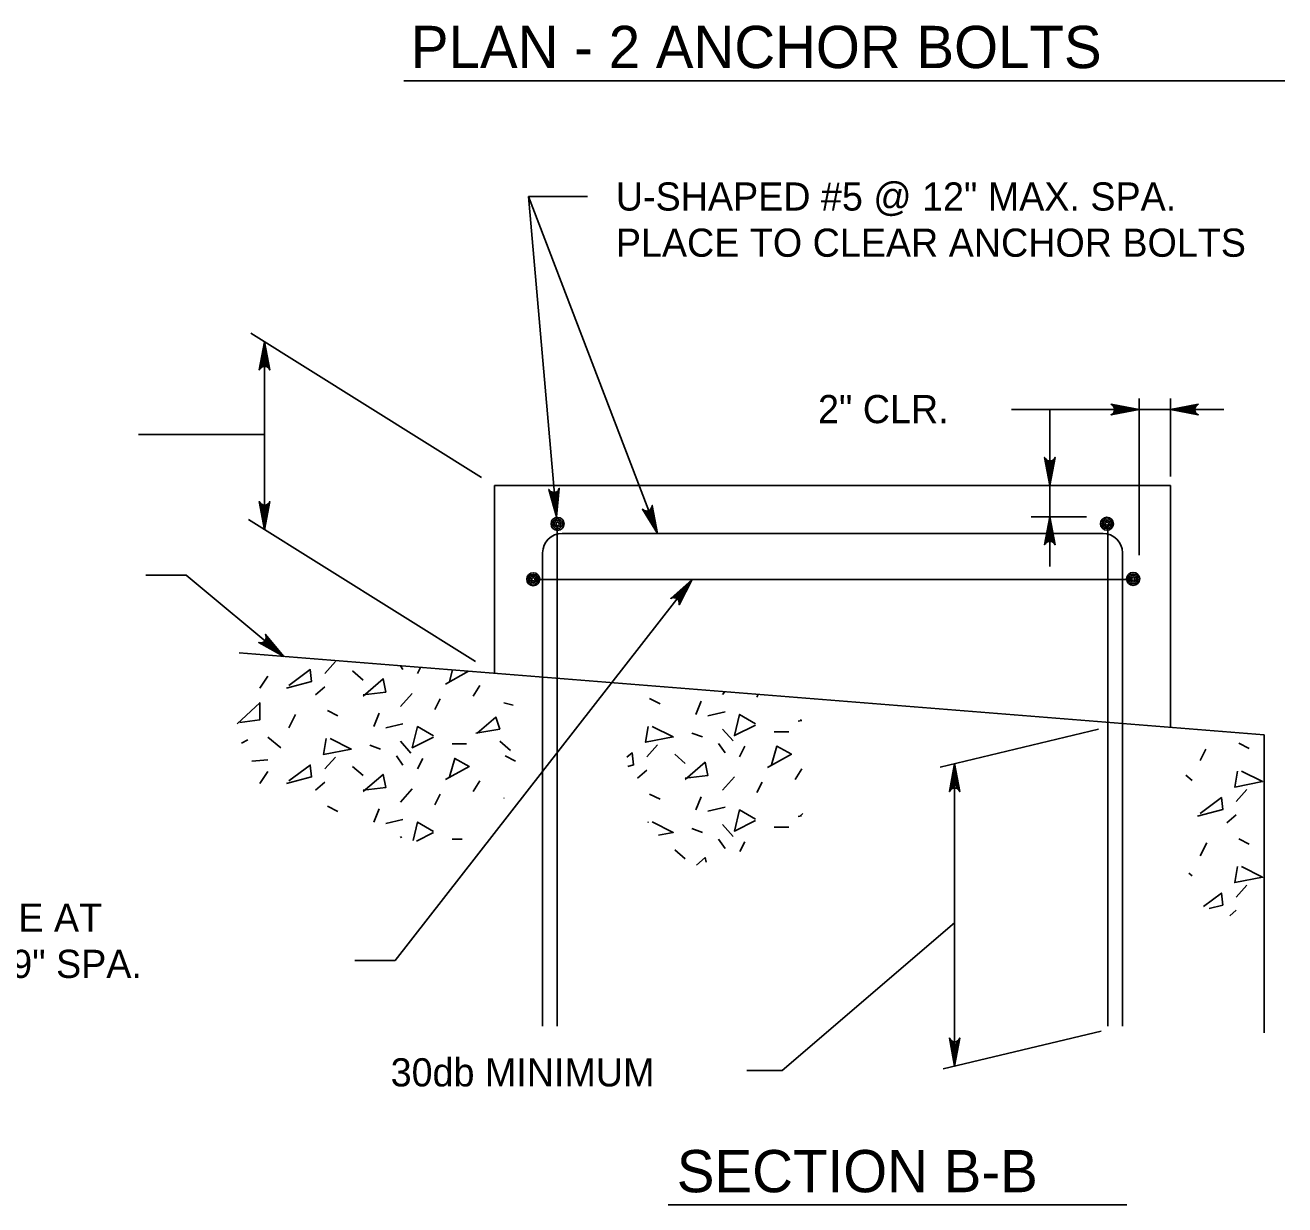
# Model space of a CAD drawing. Extents: x 646165 to 651486, y 296916 to 299292.
# Drawn here: x 651041.6 to 651175.7, y 298407.2 to 298532.8 of the extents above; entities that cross this region are included whole.
import ezdxf

# ---------------------------------------------------------------- set-up
doc = ezdxf.new("R2010")
doc.units = 0
for name, color, linetype in [('51', 7, 'Continuous'), ('52', 7, 'Continuous'), ('53', 7, 'Continuous'), ('54', 7, 'Continuous'), ('56', 7, 'Continuous')]:
    doc.layers.add(name, color=color, linetype=linetype)

msp = doc.modelspace()

# ---------------------------------------------------------------- linework, layer by layer
at = {"layer": '51'}
for p, q in [((651091.55, 298483.8), (651091.55, 298463.8)), ((651091.55, 298483.8), (651163.51, 298483.8)), ((651163.51, 298483.8), (651163.51, 298458.05)), ((651064.36, 298465.98), (651173.51, 298457.25)), ((651173.51, 298457.25), (651173.51, 298425.51))]:
    msp.add_line(p, q, dxfattribs=at)
at = {"layer": '52'}
for p, q in [((651095.17, 298514.57), (651101.44, 298514.57)), ((651095.17, 298514.57), (651098.14, 298480.47)), ((651095.17, 298514.57), (651108.88, 298478.69)), ((651065.6, 298500.01), (651090.17, 298484.66)), ((651067.05, 298499.1), (651067.05, 298479.1)), ((651160.18, 298493.07), (651160.18, 298476.38)), ((651163.51, 298493.07), (651163.51, 298484.77)), ((651146.58, 298491.89), (651169.19, 298491.89)), ((651150.68, 298491.89), (651150.68, 298475.18)), ((651053.63, 298489.22), (651067.05, 298489.22)), ((651148.69, 298480.47), (651154.57, 298480.47)), ((651065.35, 298480.17), (651089.52, 298465.07)), ((651054.42, 298474.26), (651058.71, 298474.26)), ((651069.09, 298465.6), (651058.71, 298474.26)), ((651080.96, 298433.22), (651112.58, 298473.8)), ((651138.98, 298453.82), (651155.85, 298457.85)), ((651140.54, 298454.19), (651140.54, 298421.98)), ((651122.17, 298421.51), (651140.54, 298437.23)), ((651076.67, 298433.22), (651080.96, 298433.22)), ((651139.33, 298421.69), (651156.13, 298425.7)), ((651118.41, 298421.51), (651122.17, 298421.51))]:
    msp.add_line(p, q, dxfattribs=at)
for points in [[(651067.05, 298499.1), (651067.61, 298496.12), (651067.53, 298496.24), (651067.45, 298496.35), (651067.35, 298496.41), (651067.25, 298496.47), (651067.15, 298496.49), (651067.05, 298496.5), (651066.95, 298496.49), (651066.85, 298496.47), (651066.75, 298496.41), (651066.65, 298496.35), (651066.57, 298496.24), (651066.49, 298496.12), (651067.05, 298499.1), (651066.57, 298496.24), (651066.65, 298496.35), (651067.05, 298499.1), (651066.75, 298496.41), (651066.85, 298496.47), (651067.05, 298499.1), (651066.95, 298496.49), (651067.05, 298496.5), (651067.05, 298499.1), (651067.15, 298496.49), (651067.25, 298496.47), (651067.05, 298499.1), (651067.35, 298496.41), (651067.45, 298496.35), (651067.05, 298499.1), (651067.53, 298496.24)], [(651160.18, 298491.89), (651157.2, 298491.33), (651157.31, 298491.41), (651157.43, 298491.49), (651157.48, 298491.59), (651157.54, 298491.69), (651157.56, 298491.79), (651157.58, 298491.89), (651157.56, 298491.99), (651157.54, 298492.09), (651157.48, 298492.19), (651157.43, 298492.29), (651157.31, 298492.37), (651157.2, 298492.45), (651160.18, 298491.89), (651157.31, 298492.37), (651157.43, 298492.29), (651160.18, 298491.89), (651157.48, 298492.19), (651157.54, 298492.09), (651160.18, 298491.89), (651157.56, 298491.99), (651157.58, 298491.89), (651160.18, 298491.89), (651157.56, 298491.79), (651157.54, 298491.69), (651160.18, 298491.89), (651157.48, 298491.59), (651157.43, 298491.49), (651160.18, 298491.89), (651157.31, 298491.41)], [(651163.51, 298491.89), (651166.49, 298492.45), (651166.38, 298492.37), (651166.26, 298492.29), (651166.2, 298492.19), (651166.15, 298492.09), (651166.13, 298491.99), (651166.11, 298491.89), (651166.13, 298491.79), (651166.15, 298491.69), (651166.2, 298491.59), (651166.26, 298491.49), (651166.38, 298491.41), (651166.49, 298491.33), (651163.51, 298491.89), (651166.38, 298491.41), (651166.26, 298491.49), (651163.51, 298491.89), (651166.2, 298491.59), (651166.15, 298491.69), (651163.51, 298491.89), (651166.13, 298491.79), (651166.11, 298491.89), (651163.51, 298491.89), (651166.13, 298491.99), (651166.15, 298492.09), (651163.51, 298491.89), (651166.2, 298492.19), (651166.26, 298492.29), (651163.51, 298491.89), (651166.38, 298492.37)], [(651150.68, 298483.8), (651150.12, 298486.79), (651150.2, 298486.67), (651150.28, 298486.56), (651150.38, 298486.5), (651150.48, 298486.44), (651150.58, 298486.42), (651150.68, 298486.4), (651150.78, 298486.42), (651150.88, 298486.44), (651150.98, 298486.5), (651151.08, 298486.56), (651151.16, 298486.67), (651151.24, 298486.79), (651150.68, 298483.8), (651151.16, 298486.67), (651151.08, 298486.56), (651150.68, 298483.8), (651150.98, 298486.5), (651150.88, 298486.44), (651150.68, 298483.8), (651150.78, 298486.42), (651150.68, 298486.4), (651150.68, 298483.8), (651150.58, 298486.42), (651150.48, 298486.44), (651150.68, 298483.8), (651150.38, 298486.5), (651150.28, 298486.56), (651150.68, 298483.8), (651150.2, 298486.67)], [(651098.14, 298480.47), (651097.32, 298483.39), (651097.41, 298483.28), (651097.5, 298483.18), (651097.61, 298483.13), (651097.71, 298483.08), (651097.81, 298483.07), (651097.91, 298483.06), (651098.01, 298483.08), (651098.11, 298483.11), (651098.2, 298483.18), (651098.3, 298483.25), (651098.37, 298483.37), (651098.44, 298483.49), (651098.14, 298480.47), (651098.37, 298483.37), (651098.3, 298483.25), (651098.14, 298480.47), (651098.2, 298483.18), (651098.11, 298483.11), (651098.14, 298480.47), (651098.01, 298483.08), (651097.91, 298483.06), (651098.14, 298480.47), (651097.81, 298483.07), (651097.71, 298483.08), (651098.14, 298480.47), (651097.61, 298483.13), (651097.5, 298483.18), (651098.14, 298480.47), (651097.41, 298483.28)], [(651067.05, 298479.1), (651066.49, 298482.09), (651066.57, 298481.97), (651066.65, 298481.86), (651066.75, 298481.8), (651066.85, 298481.74), (651066.95, 298481.72), (651067.05, 298481.7), (651067.15, 298481.72), (651067.25, 298481.74), (651067.35, 298481.8), (651067.45, 298481.86), (651067.53, 298481.97), (651067.61, 298482.09), (651067.05, 298479.1), (651067.53, 298481.97), (651067.45, 298481.86), (651067.05, 298479.1), (651067.35, 298481.8), (651067.25, 298481.74), (651067.05, 298479.1), (651067.15, 298481.72), (651067.05, 298481.7), (651067.05, 298479.1), (651066.95, 298481.72), (651066.85, 298481.74), (651067.05, 298479.1), (651066.75, 298481.8), (651066.65, 298481.86), (651067.05, 298479.1), (651066.57, 298481.97)], [(651108.88, 298478.69), (651107.29, 298481.28), (651107.41, 298481.2), (651107.52, 298481.12), (651107.64, 298481.1), (651107.75, 298481.08), (651107.85, 298481.1), (651107.95, 298481.12), (651108.04, 298481.17), (651108.13, 298481.23), (651108.2, 298481.32), (651108.27, 298481.41), (651108.3, 298481.54), (651108.34, 298481.68), (651108.88, 298478.69), (651108.3, 298481.54), (651108.27, 298481.41), (651108.88, 298478.69), (651108.2, 298481.32), (651108.13, 298481.23), (651108.88, 298478.69), (651108.04, 298481.17), (651107.95, 298481.12), (651108.88, 298478.69), (651107.85, 298481.1), (651107.75, 298481.08), (651108.88, 298478.69), (651107.64, 298481.1), (651107.52, 298481.12), (651108.88, 298478.69), (651107.41, 298481.2)], [(651150.68, 298480.47), (651151.24, 298477.49), (651151.16, 298477.6), (651151.08, 298477.72), (651150.98, 298477.78), (651150.88, 298477.84), (651150.78, 298477.85), (651150.68, 298477.87), (651150.58, 298477.85), (651150.48, 298477.84), (651150.38, 298477.78), (651150.28, 298477.72), (651150.2, 298477.6), (651150.12, 298477.49), (651150.68, 298480.47), (651150.2, 298477.6), (651150.28, 298477.72), (651150.68, 298480.47), (651150.38, 298477.78), (651150.48, 298477.84), (651150.68, 298480.47), (651150.58, 298477.85), (651150.68, 298477.87), (651150.68, 298480.47), (651150.78, 298477.85), (651150.88, 298477.84), (651150.68, 298480.47), (651150.98, 298477.78), (651151.08, 298477.72), (651150.68, 298480.47), (651151.16, 298477.6)], [(651112.58, 298473.8), (651111.19, 298471.11), (651111.19, 298471.25), (651111.2, 298471.39), (651111.16, 298471.49), (651111.12, 298471.6), (651111.05, 298471.68), (651110.98, 298471.75), (651110.89, 298471.8), (651110.8, 298471.85), (651110.68, 298471.86), (651110.57, 298471.88), (651110.44, 298471.84), (651110.3, 298471.79), (651112.58, 298473.8), (651110.44, 298471.84), (651110.57, 298471.88), (651112.58, 298473.8), (651110.68, 298471.86), (651110.8, 298471.85), (651112.58, 298473.8), (651110.89, 298471.8), (651110.98, 298471.75), (651112.58, 298473.8), (651111.05, 298471.68), (651111.12, 298471.6), (651112.58, 298473.8), (651111.16, 298471.49), (651111.2, 298471.39), (651112.58, 298473.8), (651111.19, 298471.25)], [(651069.09, 298465.6), (651066.44, 298467.08), (651066.58, 298467.07), (651066.72, 298467.06), (651066.83, 298467.09), (651066.94, 298467.13), (651067.02, 298467.2), (651067.1, 298467.26), (651067.15, 298467.35), (651067.2, 298467.44), (651067.22, 298467.55), (651067.23, 298467.67), (651067.2, 298467.8), (651067.16, 298467.94), (651069.09, 298465.6), (651067.2, 298467.8), (651067.23, 298467.67), (651069.09, 298465.6), (651067.22, 298467.55), (651067.2, 298467.44), (651069.09, 298465.6), (651067.15, 298467.35), (651067.1, 298467.26), (651069.09, 298465.6), (651067.02, 298467.2), (651066.94, 298467.13), (651069.09, 298465.6), (651066.83, 298467.09), (651066.72, 298467.06), (651069.09, 298465.6), (651066.58, 298467.07)], [(651140.54, 298454.19), (651141.09, 298451.21), (651140.94, 298451.44), (651140.74, 298451.56), (651140.54, 298451.59), (651140.34, 298451.56), (651140.14, 298451.44), (651139.98, 298451.21), (651140.54, 298454.19), (651140.14, 298451.44), (651140.34, 298451.56), (651140.54, 298454.19), (651140.54, 298451.59), (651140.74, 298451.56), (651140.54, 298454.19), (651140.94, 298451.44)], [(651140.54, 298421.98), (651139.98, 298424.97), (651140.14, 298424.74), (651140.34, 298424.62), (651140.54, 298424.58), (651140.74, 298424.62), (651140.94, 298424.74), (651141.09, 298424.97), (651140.54, 298421.98), (651140.94, 298424.74), (651140.74, 298424.62), (651140.54, 298421.98), (651140.54, 298424.58), (651140.34, 298424.62), (651140.54, 298421.98), (651140.14, 298424.74)]]:
    msp.add_lwpolyline(points, dxfattribs=at)
at = {"layer": '53'}
for p, q in [((651081.87, 298526.91), (651175.7, 298526.91)), ((651110.03, 298407.21), (651158.87, 298407.21))]:
    msp.add_line(p, q, dxfattribs=at)
at = {"layer": '54'}
for p, q in [((651098.22, 298479.58), (651098.22, 298426.25)), ((651156.84, 298479.58), (651156.84, 298426.25)), ((651098.73, 298478.69), (651156.34, 298478.69)), ((651096.66, 298476.63), (651096.66, 298426.25)), ((651158.4, 298476.63), (651158.4, 298426.25)), ((651095.77, 298473.8), (651159.29, 298473.8))]:
    msp.add_line(p, q, dxfattribs=at)
for centre, radius in [((651098.25, 298479.72), 0.693), ((651156.76, 298479.74), 0.693), ((651098.25, 298479.72), 0.52), ((651098.25, 298479.72), 0.347), ((651098.25, 298479.72), 0.173), ((651156.76, 298479.74), 0.52), ((651156.76, 298479.74), 0.347), ((651156.76, 298479.74), 0.173), ((651095.66, 298473.82), 0.693), ((651095.66, 298473.82), 0.52), ((651095.66, 298473.82), 0.347), ((651095.66, 298473.82), 0.173), ((651159.55, 298473.85), 0.693), ((651159.55, 298473.85), 0.52), ((651159.55, 298473.85), 0.347), ((651159.55, 298473.85), 0.173)]:
    msp.add_circle(centre, radius, dxfattribs=at)
for centre, start, end in [((651098.73, 298476.63), 90, 180), ((651156.34, 298476.63), 0, 90)]:
    msp.add_arc(centre, 2.07, start, end, dxfattribs=at)
at = {"layer": '56'}
for p, q in [((651073.46, 298463.79), (651074.59, 298465.06)), ((651081.51, 298464.61), (651081.79, 298464.21)), ((651083.67, 298464.43), (651083.35, 298463.79)), ((651066.54, 298462.23), (651067.39, 298463.5)), ((651076.43, 298464.07), (651077.56, 298463.08)), ((651072.47, 298461.53), (651073.46, 298462.37)), ((651082.78, 298461.67), (651081.51, 298460.26)), ((651089.28, 298461.39), (651089.98, 298462.52)), ((651116.08, 298461.84), (651115.81, 298461.54)), ((651119.63, 298461.56), (651119.48, 298461.26)), ((651085.75, 298461.1), (651085.18, 298459.97)), ((651092.52, 298460.68), (651093.51, 298460.4)), ((651108.04, 298461.12), (651109.17, 298460.56)), ((651113.55, 298460.84), (651112.98, 298459.43)), ((651069.65, 298458), (651070.35, 298459.41)), ((651073.74, 298459.83), (651074.87, 298459.27)), ((651079.25, 298459.55), (651078.69, 298458.14)), ((651116.09, 298459.71), (651114.26, 298459.29)), ((651081.79, 298458.42), (651079.96, 298458)), ((651115.81, 298457.87), (651116.94, 298456.6)), ((651121.32, 298457.59), (651122.87, 298457.59)), ((651065.27, 298456.73), (651064.58, 298456.38)), ((651067.39, 298457.01), (651068.8, 298455.88)), ((651081.51, 298456.58), (651082.64, 298455.31)), ((651087.02, 298456.3), (651088.57, 298456.3)), ((651092.1, 298456.58), (651093.23, 298455.6)), ((651107.76, 298454.91), (651108.89, 298456.18)), ((651112.56, 298457.45), (651113.69, 298457.03)), ((651115.39, 298456.32), (651116.09, 298455.33)), ((651170.79, 298456.36), (651171.92, 298455.8)), ((651073.46, 298453.62), (651074.59, 298454.89)), ((651078.26, 298456.16), (651079.39, 298455.74)), ((651081.09, 298455.03), (651081.79, 298454.04)), ((651092.67, 298455.03), (651093.79, 298454.47)), ((651110.73, 298455.19), (651111.85, 298454.2)), ((651118.21, 298456.04), (651117.64, 298454.91)), ((651166.69, 298454.53), (651167.3, 298455.74)), ((651065.7, 298454.47), (651067.39, 298454.61)), ((651076.43, 298453.9), (651077.56, 298452.91)), ((651083.91, 298454.75), (651083.35, 298453.62)), ((651106.77, 298452.65), (651107.76, 298453.5)), ((651123.57, 298452.51), (651124.28, 298453.64)), ((651066.54, 298452.07), (651067.39, 298453.34)), ((651072.47, 298451.36), (651073.46, 298452.21)), ((651089.28, 298451.22), (651089.98, 298452.35)), ((651117.08, 298452.79), (651115.81, 298451.38)), ((651120.04, 298452.23), (651119.48, 298451.1)), ((651165.17, 298452.95), (651165.85, 298452.41)), ((651082.78, 298451.5), (651081.51, 298450.09)), ((651085.75, 298450.94), (651085.18, 298449.81)), ((651108.04, 298450.95), (651109.17, 298450.39)), ((651170.51, 298450.15), (651171.64, 298451.42)), ((651073.74, 298449.67), (651074.87, 298449.1)), ((651092.52, 298450.51), (651092.56, 298450.5)), ((651113.55, 298450.67), (651112.98, 298449.26)), ((651116.09, 298449.54), (651114.26, 298449.12)), ((651079.25, 298449.38), (651078.69, 298447.97)), ((651081.79, 298448.25), (651079.96, 298447.83)), ((651169.52, 298447.89), (651170.51, 298448.74)), ((651112.56, 298447.28), (651113.69, 298446.86)), ((651115.81, 298447.71), (651116.94, 298446.44)), ((651121.32, 298447.42), (651122.87, 298447.42)), ((651081.51, 298446.42), (651081.63, 298446.28)), ((651087.02, 298446.14), (651088.1, 298446.14)), ((651115.39, 298446.15), (651116.09, 298445.17)), ((651118.21, 298445.87), (651117.68, 298444.82)), ((651166.69, 298444.36), (651167.4, 298445.77)), ((651170.79, 298446.19), (651171.92, 298445.63)), ((651110.73, 298445.02), (651111.85, 298444.04)), ((651165.47, 298442.54), (651165.85, 298442.24)), ((651170.51, 298439.98), (651171.64, 298441.25)), ((651169.83, 298437.99), (651170.51, 298438.57))]:
    msp.add_line(p, q, dxfattribs=at)
for points in [[(651069.37, 298462.23), (651072.05, 298462.94), (651071.91, 298464.21), (651069.65, 298462.52)], [(651077.56, 298461.53), (651079.96, 298461.81), (651079.67, 298463.22), (651077.56, 298461.39)], [(651086.31, 298462.66), (651088.77, 298464.02)], [(651087.08, 298464.16), (651086.73, 298462.94)], [(651064.42, 298458.56), (651066.54, 298458.84), (651066.54, 298460.68), (651064.14, 298458.42)], [(651089.56, 298457.43), (651092.1, 298457.86), (651091.68, 298459.13), (651089.7, 298457.43)], [(651119.34, 298458.3), (651117.08, 298457.17), (651117.64, 298459.43), (651119.34, 298458.44)], [(651124.21, 298458.9), (651124, 298458.72)], [(651085.04, 298457.01), (651082.78, 298455.88), (651083.35, 298458.14), (651085.04, 298457.15)], [(651107.9, 298458.16), (651107.62, 298456.46), (651110.58, 298457.03), (651108.32, 298458.16)], [(651123.86, 298458.72), (651124.27, 298458.79)], [(651073.6, 298456.87), (651073.32, 298455.17), (651076.29, 298455.74), (651074.03, 298456.87)], [(651105.72, 298453.9), (651106.35, 298454.06), (651106.21, 298455.33), (651105.62, 298454.89)], [(651120.61, 298453.78), (651123.15, 298455.19), (651121.6, 298456.04), (651121.03, 298454.06)], [(651069.37, 298452.07), (651072.05, 298452.77), (651071.91, 298454.04), (651069.65, 298452.35)], [(651086.31, 298452.49), (651088.85, 298453.9), (651087.3, 298454.75), (651086.73, 298452.77)], [(651111.85, 298452.65), (651114.26, 298452.93), (651113.97, 298454.34), (651111.85, 298452.51)], [(651077.56, 298451.36), (651079.96, 298451.64), (651079.67, 298453.05), (651077.56, 298451.22)], [(651170.65, 298453.4), (651170.37, 298451.7), (651173.33, 298452.27), (651171.07, 298453.4)], [(651166.41, 298448.59), (651169.09, 298449.3), (651168.95, 298450.57), (651166.69, 298448.88)], [(651119.34, 298448.13), (651117.08, 298447), (651117.64, 298449.26), (651119.34, 298448.27)], [(651123.86, 298448.55), (651124.24, 298448.62)], [(651124.39, 298448.89), (651124, 298448.55)], [(651082.86, 298446.02), (651083.35, 298447.97), (651085.04, 298446.98)], [(651085.04, 298446.84), (651083.24, 298445.94)], [(651107.9, 298447.99), (651107.89, 298447.93)], [(651109, 298446.56), (651110.58, 298446.86), (651108.32, 298447.99)], [(651114.07, 298443.7), (651113.97, 298444.18), (651113.06, 298443.38)], [(651170.65, 298443.23), (651170.37, 298441.53), (651173.33, 298442.1), (651171.07, 298443.23)], [(651167.64, 298438.75), (651169.09, 298439.13), (651168.95, 298440.4), (651167.03, 298438.96)]]:
    msp.add_lwpolyline(points, dxfattribs=at)

# ---------------------------------------------------------------- texts
at = {"layer": '53'}
for s, height, p in [('PLAN - 2 ANCHOR BOLTS', 4.5, (651082.63, 298528.25)), ('U-SHAPED #5 @ 12" MAX. SPA.', 3, (651104.46, 298513.08)), ('PLACE TO CLEAR ANCHOR BOLTS', 3, (651104.46, 298508.16)), ('2" CLR.', 3, (651125.99, 298490.44)), ('HEIGHT EXCEEDS 8". PLACE AT', 3, (650987.91, 298436.29)), ('1/2 PEDSETAL HEIGHT OR 9" SPA.', 3, (650987.91, 298431.37)), ('30db MINIMUM', 3, (651080.48, 298419.82)), ('SECTION B-B', 4.5, (651110.95, 298408.55))]:
    msp.add_text(s, height=height, dxfattribs=at).set_placement(p)

doc.saveas('drawing.dxf')
